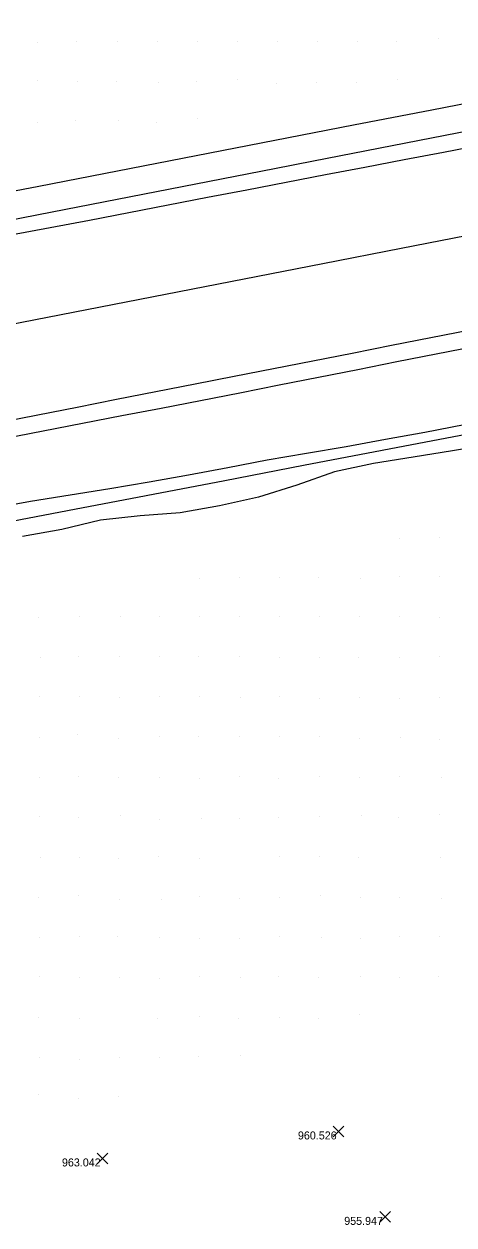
# Model space of a CAD drawing. Extents: x 2262025 to 2264532, y 740981 to 742724.
# Drawn here: x 2262920.9 to 2262974.6, y 741893.1 to 742043.1 of the extents above; entities that cross this region are included whole.
import ezdxf

# ---------------------------------------------------------------- set-up
doc = ezdxf.new("R2010")
doc.units = 0
for name, color, linetype in [('GE_X_Alignment_1000_Curve_Data', 7, 'Continuous'), ('GE_X_Alignment_100_Bearings', 7, 'Continuous'), ('GE_X_Alignment_100_Curve_Data', 7, 'Continuous'), ('GE_X_Alignment_500_Cardinal_Points', 7, 'Continuous'), ('Ground Shots', 7, 'Continuous'), ('HY_X_Spring_Cells', 7, 'Continuous'), ('RW_X_CL_1000_Distances', 7, 'Continuous'), ('SC_Scratch2', 7, 'Continuous'), ('SV_X_Control_Cells_Found', 7, 'Continuous')]:
    doc.layers.add(name, color=color, linetype=linetype)

msp = doc.modelspace()

# ---------------------------------------------------------------- linework, layer by layer
at = {"layer": 'GE_X_Alignment_1000_Curve_Data'}
for points in [[(2262917.84, 742018.4), (2262922.75, 742019.36), (2262927.65, 742020.31), (2262932.56, 742021.26), (2262937.47, 742022.22), (2262942.38, 742023.17), (2262947.29, 742024.12), (2262952.2, 742025.08), (2262957.1, 742026.03), (2262962.01, 742026.99), (2262966.92, 742027.95), (2262971.83, 742028.9), (2262976.73, 742029.86)], [(2262918.43, 741991.38), (2262923.34, 741992.33), (2262928.25, 741993.27), (2262933.16, 741994.22), (2262938.07, 741995.17), (2262942.98, 741996.11), (2262947.88, 741997.08), (2262952.79, 741998.05), (2262957.69, 741999.02), (2262962.6, 741999.99), (2262967.5, 742000.96), (2262972.41, 742001.92), (2262977.31, 742002.89), (2262982.22, 742003.86), (2262987.13, 742004.83), (2262992.03, 742005.8), (2262996.94, 742006.77), (2263001.84, 742007.73), (2263006.75, 742008.7), (2263011.65, 742009.67), (2263016.56, 742010.64), (2263021.46, 742011.61), (2263021.48, 742011.61)]]:
    msp.add_lwpolyline(points, dxfattribs=at)
at = {"layer": 'GE_X_Alignment_100_Bearings'}
msp.add_lwpolyline([(2262916.55, 741980.49), (2262926.37, 741982.37), (2262936.2, 741984.25), (2262946.02, 741986.13), (2262955.84, 741988.01), (2262965.66, 741989.9), (2262975.48, 741991.78), (2262985.3, 741993.66), (2262995.12, 741995.54), (2263004.94, 741997.43), (2263014.77, 741999.31), (2263024.59, 742001.19), (2263034.41, 742003.07), (2263044.22, 742004.98), (2263054.04, 742006.91), (2263063.85, 742008.84), (2263073.66, 742010.78), (2263083.47, 742012.71), (2263093.28, 742014.64), (2263103.09, 742016.57), (2263112.91, 742018.5), (2263122.72, 742020.43), (2263132.53, 742022.36), (2263139.69, 742023.77)], dxfattribs=at)
at = {"layer": 'GE_X_Alignment_100_Curve_Data'}
for points in [[(2262912.97, 742021), (2262922.79, 742022.89), (2262932.61, 742024.8), (2262942.42, 742026.7), (2262952.24, 742028.61), (2262962.06, 742030.52), (2262971.87, 742032.43), (2262981.69, 742034.34), (2262991.5, 742036.25), (2263001.32, 742038.15), (2263011.14, 742040.05), (2263020.96, 742041.95), (2263030.77, 742043.86)], [(2262975.91, 741993.06), (2262971, 741992.11), (2262966.08, 741991.22), (2262961.16, 741990.33), (2262956.23, 741989.49), (2262951.3, 741988.64), (2262946.39, 741987.71), (2262941.48, 741986.78), (2262936.55, 741985.92), (2262931.63, 741985.06), (2262926.69, 741984.28), (2262921.75, 741983.49), (2262916.96, 741982.61)]]:
    msp.add_lwpolyline(points, dxfattribs=at)
at = {"layer": 'GE_X_Alignment_500_Cardinal_Points'}
for p, q in [((2262959.54, 741904.14), (2262960.87, 741905.47)), ((2262959.54, 741905.47), (2262960.87, 741904.14)), ((2262930.06, 741900.77), (2262931.39, 741902.1)), ((2262930.06, 741902.1), (2262931.39, 741900.77)), ((2262965.36, 741893.47), (2262966.69, 741894.81)), ((2262965.36, 741894.81), (2262966.69, 741893.47))]:
    msp.add_line(p, q, dxfattribs=at)
at = {"layer": 'Ground Shots'}
for p, q in [((2262922.62, 742040.88), (2262922.62, 742040.88)), ((2262927.54, 742040.97), (2262927.54, 742040.97)), ((2262932.62, 742040.91), (2262932.62, 742040.91)), ((2262937.58, 742040.89), (2262937.58, 742040.89)), ((2262942.59, 742040.94), (2262942.59, 742040.94)), ((2262947.58, 742040.93), (2262947.58, 742040.93)), ((2262952.58, 742040.9), (2262952.58, 742040.9)), ((2262957.58, 742040.92), (2262957.58, 742040.92)), ((2262962.57, 742040.97), (2262962.57, 742040.97)), ((2262967.5, 742040.95), (2262967.5, 742040.95)), ((2262972.64, 742041.33), (2262972.64, 742041.33)), ((2262967.57, 742036.26), (2262967.57, 742036.26)), ((2262922.63, 742036.11), (2262922.63, 742036.11)), ((2262927.55, 742035.89), (2262927.55, 742035.89)), ((2262932.44, 742035.91), (2262932.44, 742035.91)), ((2262937.71, 742035.81), (2262937.71, 742035.81)), ((2262942.53, 742035.9), (2262942.53, 742035.9)), ((2262947.65, 742036.17), (2262947.65, 742036.17)), ((2262952.43, 742035.76), (2262952.43, 742035.76)), ((2262957.41, 742035.83), (2262957.41, 742035.83)), ((2262962.44, 742035.78), (2262962.44, 742035.78)), ((2262922.62, 742030.89), (2262922.62, 742030.89)), ((2262927.35, 742031.04), (2262927.35, 742031.04)), ((2262932.71, 742031.12), (2262932.71, 742031.12)), ((2262937.47, 742030.84), (2262937.47, 742030.84)), ((2262942.56, 742031.33), (2262942.56, 742031.33)), ((2262967.8, 741978.84), (2262967.8, 741978.84)), ((2262972.86, 741979.05), (2262972.86, 741979.05)), ((2262942.81, 741973.85), (2262942.81, 741973.85)), ((2262947.8, 741973.95), (2262947.8, 741973.95)), ((2262952.78, 741974.04), (2262952.78, 741974.04)), ((2262957.77, 741973.97), (2262957.77, 741973.97)), ((2262962.93, 741973.85), (2262962.93, 741973.85)), ((2262967.78, 741974.1), (2262967.78, 741974.1)), ((2262972.87, 741974.07), (2262972.87, 741974.07)), ((2262922.8, 741969.04), (2262922.8, 741969.04)), ((2262927.87, 741969.08), (2262927.87, 741969.08)), ((2262932.96, 741969.19), (2262932.96, 741969.19)), ((2262937.8, 741969.1), (2262937.8, 741969.1)), ((2262942.84, 741969.12), (2262942.84, 741969.12)), ((2262947.82, 741969.15), (2262947.82, 741969.15)), ((2262952.8, 741969.08), (2262952.8, 741969.08)), ((2262957.8, 741969.16), (2262957.8, 741969.16)), ((2262962.82, 741969.14), (2262962.82, 741969.14)), ((2262967.81, 741969.07), (2262967.81, 741969.07)), ((2262972.82, 741968.98), (2262972.82, 741968.98)), ((2262922.96, 741963.99), (2262922.96, 741963.99)), ((2262927.78, 741964.12), (2262927.78, 741964.12)), ((2262932.84, 741964.16), (2262932.84, 741964.16)), ((2262937.79, 741964.16), (2262937.79, 741964.16)), ((2262942.76, 741964.08), (2262942.76, 741964.08)), ((2262947.8, 741964.14), (2262947.8, 741964.14)), ((2262952.83, 741964.01), (2262952.83, 741964.01)), ((2262957.82, 741964.04), (2262957.82, 741964.04)), ((2262962.67, 741963.99), (2262962.67, 741963.99)), ((2262967.87, 741964.02), (2262967.87, 741964.02)), ((2262972.76, 741964.08), (2262972.76, 741964.08)), ((2262922.82, 741959.08), (2262922.82, 741959.08)), ((2262927.82, 741959.13), (2262927.82, 741959.13)), ((2262932.82, 741959.06), (2262932.82, 741959.06)), ((2262937.81, 741959.13), (2262937.81, 741959.13)), ((2262942.79, 741959.17), (2262942.79, 741959.17)), ((2262947.99, 741959.06), (2262947.99, 741959.06)), ((2262952.86, 741959.12), (2262952.86, 741959.12)), ((2262957.89, 741958.9), (2262957.89, 741958.9)), ((2262962.85, 741958.97), (2262962.85, 741958.97)), ((2262967.84, 741958.9), (2262967.84, 741958.9)), ((2262972.83, 741959.04), (2262972.83, 741959.04)), ((2262922.88, 741953.98), (2262922.88, 741953.98)), ((2262927.65, 741954.39), (2262927.65, 741954.39)), ((2262932.78, 741953.94), (2262932.78, 741953.94)), ((2262937.8, 741954.08), (2262937.8, 741954.08)), ((2262942.78, 741954.08), (2262942.78, 741954.08)), ((2262947.84, 741954.09), (2262947.84, 741954.09)), ((2262952.8, 741954.08), (2262952.8, 741954.08)), ((2262957.8, 741954.12), (2262957.8, 741954.12)), ((2262962.89, 741953.83), (2262962.89, 741953.83)), ((2262967.89, 741953.97), (2262967.89, 741953.97)), ((2262972.79, 741953.82), (2262972.79, 741953.82)), ((2262922.83, 741948.99), (2262922.83, 741948.99)), ((2262927.75, 741949.12), (2262927.75, 741949.12)), ((2262932.77, 741949.06), (2262932.77, 741949.06)), ((2262937.79, 741948.96), (2262937.79, 741948.96)), ((2262942.89, 741948.89), (2262942.89, 741948.89)), ((2262947.83, 741949.12), (2262947.83, 741949.12)), ((2262952.69, 741948.95), (2262952.69, 741948.95)), ((2262957.84, 741949.17), (2262957.84, 741949.17)), ((2262962.85, 741949.07), (2262962.85, 741949.07)), ((2262967.8, 741949.09), (2262967.8, 741949.09)), ((2262973.11, 741949.02), (2262973.11, 741949.02)), ((2262922.83, 741944.12), (2262922.83, 741944.12)), ((2262927.78, 741944.07), (2262927.78, 741944.07)), ((2262933, 741944.25), (2262933, 741944.25)), ((2262937.83, 741943.79), (2262937.83, 741943.79)), ((2262943.11, 741943.88), (2262943.11, 741943.88)), ((2262947.82, 741943.9), (2262947.82, 741943.9)), ((2262952.69, 741944.06), (2262952.69, 741944.06)), ((2262957.81, 741944.1), (2262957.81, 741944.1)), ((2262963.02, 741944.28), (2262963.02, 741944.28)), ((2262967.75, 741943.99), (2262967.75, 741943.99)), ((2262972.76, 741944.41), (2262972.76, 741944.41)), ((2262922.98, 741939.02), (2262922.98, 741939.02)), ((2262927.84, 741939.04), (2262927.84, 741939.04)), ((2262932.73, 741938.87), (2262932.73, 741938.87)), ((2262937.73, 741939.11), (2262937.73, 741939.11)), ((2262942.82, 741938.96), (2262942.82, 741938.96)), ((2262952.84, 741939.1), (2262952.84, 741939.1)), ((2262957.84, 741939.13), (2262957.84, 741939.13)), ((2262962.74, 741938.97), (2262962.74, 741938.97)), ((2262972.97, 741938.98), (2262972.97, 741938.98)), ((2262927.72, 741934.24), (2262927.72, 741934.24)), ((2262957.95, 741934.22), (2262957.95, 741934.22)), ((2262922.79, 741934.06), (2262922.79, 741934.06)), ((2262932.87, 741933.83), (2262932.87, 741933.83)), ((2262938.07, 741933.84), (2262938.07, 741933.84)), ((2262942.9, 741934.17), (2262942.9, 741934.17)), ((2262947.84, 741933.96), (2262947.84, 741933.96)), ((2262952.82, 741934.05), (2262952.82, 741934.05)), ((2262962.95, 741934), (2262962.95, 741934)), ((2262967.88, 741933.97), (2262967.88, 741933.97)), ((2262973.04, 741933.88), (2262973.04, 741933.88)), ((2262922.91, 741929.02), (2262922.91, 741929.02)), ((2262927.85, 741929.13), (2262927.85, 741929.13)), ((2262932.64, 741929.16), (2262932.64, 741929.16)), ((2262937.86, 741928.99), (2262937.86, 741928.99)), ((2262942.8, 741928.87), (2262942.8, 741928.87)), ((2262947.79, 741928.97), (2262947.79, 741928.97)), ((2262952.8, 741929.1), (2262952.8, 741929.1)), ((2262958.03, 741929.02), (2262958.03, 741929.02)), ((2262962.95, 741928.85), (2262962.95, 741928.85)), ((2262967.88, 741929.15), (2262967.88, 741929.15)), ((2262972.84, 741929.13), (2262972.84, 741929.13)), ((2262922.84, 741924.15), (2262922.84, 741924.15)), ((2262927.87, 741924), (2262927.87, 741924)), ((2262932.8, 741924.06), (2262932.8, 741924.06)), ((2262937.9, 741923.96), (2262937.9, 741923.96)), ((2262942.87, 741924.14), (2262942.87, 741924.14)), ((2262947.94, 741924.07), (2262947.94, 741924.07)), ((2262952.76, 741924.18), (2262952.76, 741924.18)), ((2262957.71, 741924.08), (2262957.71, 741924.08)), ((2262962.91, 741924.18), (2262962.91, 741924.18)), ((2262967.85, 741924), (2262967.85, 741924)), ((2262972.68, 741924.18), (2262972.68, 741924.18)), ((2262962.77, 741919.4), (2262962.77, 741919.4)), ((2262922.78, 741919.05), (2262922.78, 741919.05)), ((2262927.9, 741918.88), (2262927.9, 741918.88)), ((2262937.63, 741918.93), (2262937.63, 741918.93)), ((2262942.85, 741919.14), (2262942.85, 741919.14)), ((2262947.71, 741918.9), (2262947.71, 741918.9)), ((2262952.83, 741919.09), (2262952.83, 741919.09)), ((2262957.65, 741918.91), (2262957.65, 741918.91)), ((2262922.86, 741914.06), (2262922.86, 741914.06)), ((2262927.8, 741913.83), (2262927.8, 741913.83)), ((2262932.91, 741914.07), (2262932.91, 741914.07)), ((2262937.79, 741913.99), (2262937.79, 741913.99)), ((2262942.71, 741914.18), (2262942.71, 741914.18)), ((2262947.95, 741914.24), (2262947.95, 741914.24)), ((2262922.69, 741909.37), (2262922.69, 741909.37)), ((2262927.79, 741908.98), (2262927.79, 741908.98)), ((2262932.76, 741909.12), (2262932.76, 741909.12))]:
    msp.add_line(p, q, dxfattribs=at)
at = {"layer": 'RW_X_CL_1000_Distances'}
for points in [[(2262919.3, 742016.78), (2262924.21, 742017.72), (2262929.12, 742018.65), (2262934.04, 742019.59), (2262938.95, 742020.54), (2262943.85, 742021.49), (2262948.76, 742022.43), (2262953.67, 742023.38), (2262958.58, 742024.32), (2262963.49, 742025.26), (2262968.4, 742026.2), (2262973.31, 742027.14), (2262978.22, 742028.09)], [(2262917.76, 741993.37), (2262922.66, 741994.33), (2262927.57, 741995.29), (2262932.47, 741996.26), (2262937.38, 741997.22), (2262942.29, 741998.18), (2262947.19, 741999.15), (2262952.1, 742000.11), (2262957.01, 742001.07), (2262961.91, 742002.03), (2262966.82, 742003), (2262971.73, 742003.96), (2262976.63, 742004.92)]]:
    msp.add_lwpolyline(points, dxfattribs=at)
at = {"layer": 'SC_Scratch2'}
msp.add_lwpolyline([(2262918.97, 742005.55), (2262928.79, 742007.46), (2262938.6, 742009.37), (2262948.42, 742011.29), (2262958.23, 742013.2), (2262968.05, 742015.12), (2262977.86, 742017.03), (2262987.68, 742018.94), (2262997.5, 742020.86), (2263007.31, 742022.75), (2263017.13, 742024.65), (2263026.95, 742026.54), (2263036.77, 742028.44), (2263046.59, 742030.33), (2263056.41, 742032.22), (2263066.23, 742034.12), (2263076.05, 742036.01), (2263085.87, 742037.9), (2263095.69, 742039.8), (2263105.5, 742041.69), (2263115.32, 742043.59)], dxfattribs=at)
at = {"layer": 'SV_X_Control_Cells_Found'}
msp.add_lwpolyline([(2262984.33, 741991.43), (2262974.46, 741989.82), (2262969.53, 741989.02), (2262964.59, 741988.22), (2262959.72, 741987.18), (2262955, 741985.53), (2262950.23, 741984.04), (2262945.35, 741982.97), (2262940.44, 741982.09), (2262935.45, 741981.72), (2262930.5, 741981.14), (2262925.64, 741979.98), (2262920.74, 741979.13)], dxfattribs=at)

# ---------------------------------------------------------------- texts
at = {"layer": 'HY_X_Spring_Cells'}
for s, p in [('960.526', (2262955.14, 741903.81)), ('963.042', (2262925.67, 741900.44)), ('955.947', (2262960.92, 741893.14))]:
    msp.add_text(s, height=1, dxfattribs=at).set_placement(p)

doc.saveas('drawing.dxf')
